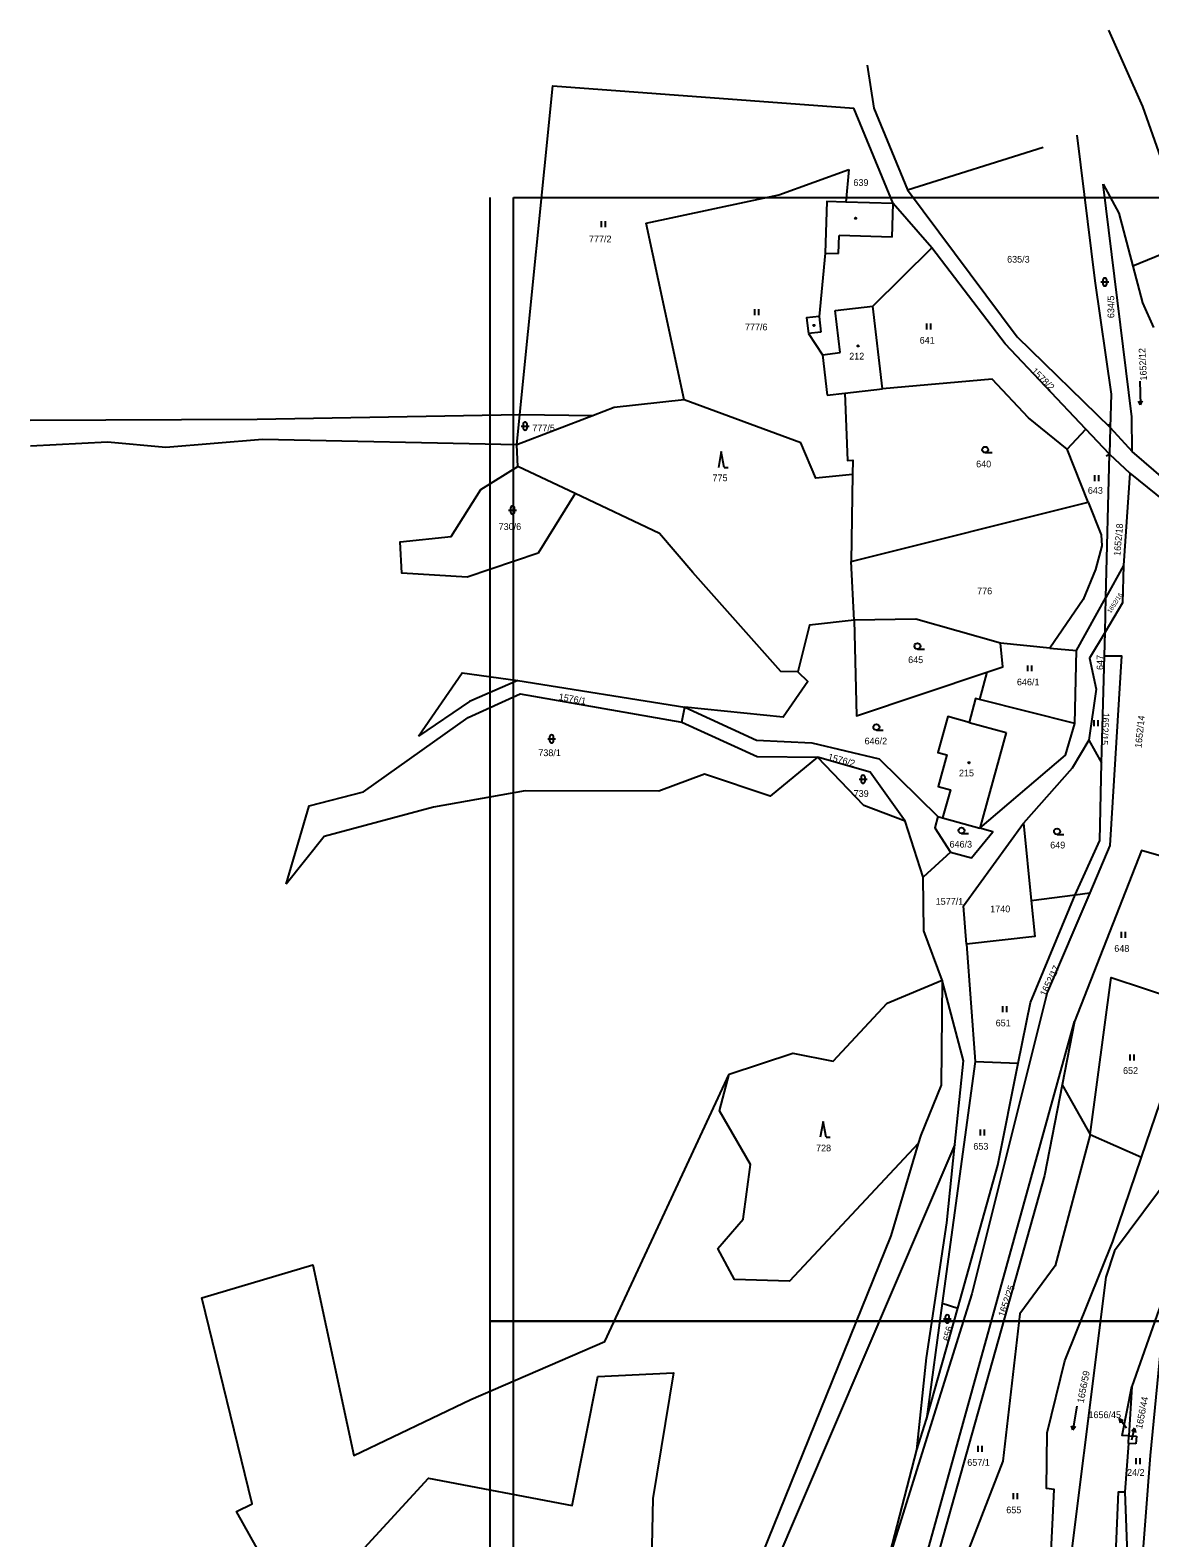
# Model space of a CAD drawing. Extents: x -553916 to -552953, y -1067470 to -1066637.
# Drawn here: x -553916.1 to -553633.4, y -1067154.7 to -1066774 of the extents above; entities that cross this region are included whole.
import ezdxf

# ---------------------------------------------------------------- set-up
doc = ezdxf.new("R2010")
doc.units = 0
for name, color, linetype in [('Hranice parcel', 7, 'Continuous'), ('Parcelní čísla', 7, 'Continuous'), ('Pop  PČ popisy', 7, 'Continuous'), ('Vnitřní kresba', 7, 'Continuous'), ('Vrstva 1', 7, 'Continuous'), ('Značky budov', 7, 'Continuous'), ('Značky kultur', 7, 'Continuous')]:
    doc.layers.add(name, color=color, linetype=linetype)

msp = doc.modelspace()

# ---------------------------------------------------------------- linework, layer by layer
at = {"layer": 'Hranice parcel'}
for p, q in [((-553698.19, -1066817.82), (-553708.14, -1066793.72)), ((-553694.61, -1066814.35), (-553660.35, -1066803.56)), ((-553727.1, -1066815.64), (-553709.46, -1066809.18)), ((-553709.46, -1066809.18), (-553710.17, -1066817.45)), ((-553760.56, -1066822.8), (-553727.1, -1066815.64)), ((-553698.19, -1066817.82), (-553710.17, -1066817.45)), ((-553688.48, -1066828.98), (-553698.19, -1066817.82)), ((-553750.96, -1066867.38), (-553760.56, -1066822.8)), ((-553623.67, -1066827.87), (-553637.71, -1066833.62)), ((-553710.42, -1066865.69), (-553700.89, -1066864.57)), ((-553714.89, -1066866.21), (-553710.42, -1066865.69)), ((-553793.21, -1066878.75), (-553792.44, -1066871.07)), ((-553773.88, -1066871.32), (-553793.21, -1066878.75)), ((-553792.44, -1066871.07), (-553773.88, -1066871.32)), ((-553654.33, -1066879.84), (-553649.57, -1066874.82)), ((-553643.58, -1066881.05), (-553649.57, -1066874.82)), ((-553643.41, -1066874.34), (-553637.93, -1066880.39)), ((-553792.95, -1066884.2), (-553793.21, -1066878.75)), ((-553648.98, -1066893.19), (-553654.33, -1066879.84)), ((-553629.4, -1066887.71), (-553637.93, -1066880.39)), ((-553778.5, -1066891.03), (-553792.95, -1066884.2)), ((-553644.51, -1066917.3), (-553643.58, -1066881.05)), ((-553643.58, -1066881.05), (-553638.51, -1066885.89)), ((-553708.48, -1066886.24), (-553708.86, -1066908.17)), ((-553638.51, -1066885.89), (-553640.1, -1066909.21)), ((-553708.86, -1066908.17), (-553648.98, -1066893.19)), ((-553708.1, -1066923.04), (-553708.86, -1066908.17)), ((-553640.1, -1066909.21), (-553644.51, -1066917.3)), ((-553651.92, -1066930.68), (-553644.51, -1066917.3)), ((-553644.74, -1066926.04), (-553644.51, -1066917.3)), ((-553644.89, -1066931.97), (-553644.74, -1066926.04)), ((-553658.66, -1066930.04), (-553671.16, -1066928.84)), ((-553658.66, -1066930.04), (-553651.92, -1066930.68)), ((-553652.33, -1066949.09), (-553651.92, -1066930.68)), ((-553645.59, -1066958.99), (-553644.89, -1066931.97)), ((-553674.58, -1066936.12), (-553676.4, -1066943.07)), ((-553793.02, -1066938.22), (-553750.82, -1066944.94)), ((-553751.58, -1066948.77), (-553750.82, -1066944.94)), ((-553652.33, -1066949.09), (-553676.4, -1066943.07)), ((-553648.85, -1066953.28), (-553645.59, -1066958.99)), ((-553690.64, -1066987.88), (-553695.17, -1066973.73)), ((-553686.98, -1066972.56), (-553685.74, -1066972.91)), ((-553685.74, -1066972.91), (-553676.37, -1066975.51)), ((-553665.3, -1066974.22), (-553663.36, -1066993.83)), ((-553683.73, -1066981.56), (-553690.64, -1066987.88)), ((-553663.36, -1066993.83), (-553652.32, -1066992.37)), ((-553652.32, -1066992.37), (-553648.57, -1066991.82)), ((-553679.73, -1067004.79), (-553677.51, -1067034.42)), ((-553652.47, -1067024.37), (-553655.53, -1067040.29)), ((-553677.51, -1067034.42), (-553685.85, -1067095.42)), ((-553677.51, -1067034.42), (-553666.64, -1067034.88)), ((-553655.53, -1067040.29), (-553648.45, -1067052.9)), ((-553682.64, -1067055.36), (-553736.85, -1067182.11)), ((-553648.45, -1067052.9), (-553635.52, -1067058.6)), ((-553642.79, -1067079.87), (-553635.52, -1067058.6)), ((-553685.85, -1067095.42), (-553689.85, -1067124.72)), ((-553689.85, -1067124.72), (-553681.91, -1067096.73)), ((-553685.85, -1067095.42), (-553681.91, -1067096.73)), ((-553637.98, -1067116.48), (-553638.7, -1067128.96)), ((-553692.26, -1067132.51), (-553689.85, -1067124.72)), ((-553638.81, -1067130.87), (-553639.7, -1067143.1)), ((-553638.81, -1067130.87), (-553638.7, -1067128.96)), ((-553636.94, -1067130.98), (-553638.81, -1067130.87)), ((-553638.7, -1067128.96), (-553636.8, -1067129.04)), ((-553636.8, -1067129.04), (-553636.94, -1067130.98)), ((-553699.64, -1067161.1), (-553692.26, -1067132.51)), ((-553639.7, -1067143.1), (-553638.95, -1067163.99))]:
    msp.add_line(p, q, dxfattribs=at)
for points in [[(-553643.88, -1066774.03), (-553635.29, -1066793.34), (-553625.66, -1066820.5)], [(-553704.82, -1066782.89), (-553703.1, -1066793.75), (-553694.61, -1066814.35)], [(-553792.44, -1066871.07), (-553784.13, -1066788.1), (-553708.14, -1066793.72)], [(-553651.89, -1066800.53), (-553647.31, -1066837.34), (-553643.19, -1066865.93), (-553643.41, -1066874.34)], [(-553694.61, -1066814.35), (-553666.95, -1066851.46), (-553643.41, -1066874.34)], [(-553637.93, -1066880.39), (-553637.95, -1066871.66), (-553645.19, -1066812.95)], [(-553645.19, -1066812.95), (-553641.24, -1066820.26), (-553637.71, -1066833.62)], [(-553710.17, -1066817.45), (-553715.01, -1066817.3), (-553715.41, -1066830.35), (-553716.91, -1066846.31), (-553720.09, -1066846.68), (-553719.63, -1066850.66)], [(-553700.89, -1066864.57), (-553703.32, -1066843.72), (-553688.48, -1066828.98)], [(-553649.57, -1066874.82), (-553669.94, -1066853.22), (-553688.48, -1066828.98)], [(-553637.71, -1066833.62), (-553635.67, -1066841.32), (-553635.29, -1066842.84), (-553632.51, -1066849.1)], [(-553719.63, -1066850.66), (-553716.09, -1066855.98), (-553714.89, -1066866.21)], [(-553654.33, -1066879.84), (-553664.06, -1066871.9), (-553673.22, -1066862.17), (-553700.89, -1066864.57)], [(-553750.96, -1066867.38), (-553768.66, -1066869.31), (-553773.88, -1066871.32)], [(-553708.48, -1066886.24), (-553717.76, -1066887.14), (-553721.5, -1066878.2), (-553750.96, -1066867.38)], [(-553710.42, -1066865.69), (-553709.75, -1066882.68), (-553708.42, -1066882.64), (-553708.48, -1066886.24)], [(-553916.1, -1066872.49), (-553858.75, -1066872.29), (-553792.44, -1066871.07)], [(-553793.21, -1066878.75), (-553857.42, -1066877.37), (-553881.82, -1066879.37), (-553896.57, -1066878.03), (-553915.98, -1066879.03)], [(-553778.5, -1066891.03), (-553787.89, -1066906.11), (-553805.77, -1066912.16), (-553822.27, -1066911.17), (-553822.69, -1066903.26), (-553809.84, -1066901.91), (-553802.35, -1066890.01), (-553792.95, -1066884.2)], [(-553638.51, -1066885.89), (-553629.69, -1066892.95), (-553626.61, -1066895.43)], [(-553722.33, -1066936.07), (-553726.59, -1066935.94), (-553748.79, -1066910.99), (-553757.18, -1066901.11), (-553778.5, -1066891.03)], [(-553648.98, -1066893.19), (-553645.71, -1066901.42), (-553645.52, -1066904.26), (-553647.18, -1066910.25), (-553650.27, -1066917.79), (-553658.66, -1066930.04)], [(-553640.1, -1066909.21), (-553640.34, -1066918.66), (-553644.74, -1066926.04)], [(-553708.1, -1066923.04), (-553719.33, -1066924.26), (-553722.33, -1066936.07)], [(-553671.16, -1066928.84), (-553692.53, -1066922.74), (-553708.1, -1066923.04)], [(-553708.1, -1066923.04), (-553707.52, -1066947.12), (-553674.58, -1066936.12)], [(-553644.74, -1066926.04), (-553648.66, -1066932.61), (-553646.94, -1066940.41), (-553648.85, -1066953.28)], [(-553674.58, -1066936.12), (-553670.5, -1066934.76), (-553671.16, -1066928.84)], [(-553644.89, -1066931.97), (-553640.62, -1066932.03), (-553643.49, -1066979.92), (-553648.57, -1066991.82)], [(-553818.03, -1066952.27), (-553807.07, -1066936.29), (-553793.02, -1066938.22)], [(-553722.33, -1066936.07), (-553719.8, -1066938.45), (-553726.01, -1066947.52), (-553750.82, -1066944.94)], [(-553793.02, -1066938.22), (-553805.16, -1066943.52), (-553818.03, -1066952.27)], [(-553851.45, -1066989.66), (-553845.69, -1066969.91), (-553831.91, -1066966.35), (-553805.48, -1066947.58), (-553792.42, -1066941.62), (-553751.58, -1066948.77)], [(-553750.82, -1066944.94), (-553732.69, -1066953.28), (-553718.72, -1066954.01), (-553701.74, -1066958), (-553686.98, -1066972.56)], [(-553676.4, -1066943.07), (-553677.43, -1066942.81), (-553679, -1066948.83), (-553684.45, -1066947.32), (-553686.97, -1066956.38), (-553684.65, -1066957.02), (-553686.87, -1066965.02), (-553683.79, -1066965.88), (-553685.74, -1066972.91)], [(-553751.58, -1066948.77), (-553732.58, -1066957.42), (-553717.29, -1066957.56)], [(-553676.37, -1066975.51), (-553654.76, -1066957.08), (-553652.33, -1066949.09)], [(-553648.85, -1066953.28), (-553653.03, -1066960.38), (-553665.3, -1066974.22)], [(-553717.29, -1066957.56), (-553729.27, -1066967.46), (-553745.82, -1066961.92), (-553757.37, -1066966.16), (-553791.09, -1066966.12), (-553814.24, -1066970.19), (-553841.88, -1066977.67), (-553851.45, -1066989.66)], [(-553695.17, -1066973.73), (-553705.64, -1066969.81), (-553717.29, -1066957.56)], [(-553695.17, -1066973.73), (-553704.05, -1066961.37), (-553717.29, -1066957.56)], [(-553652.32, -1066992.37), (-553646.09, -1066978.61), (-553645.59, -1066958.99)], [(-553686.98, -1066972.56), (-553687.7, -1066975.46), (-553683.73, -1066981.56)], [(-553683.73, -1066981.56), (-553678.45, -1066983.01), (-553673.1, -1066976.42), (-553676.37, -1066975.51)], [(-553679.73, -1067004.79), (-553680.45, -1066995.12), (-553665.3, -1066974.22)], [(-553627.02, -1066983.6), (-553635.52, -1066981.16), (-553652.47, -1067024.37)], [(-553623.32, -1066984.67), (-553619.63, -1066996.83), (-553619.56, -1067023.02), (-553621.7, -1067038.64), (-553627.75, -1067062.69), (-553642.34, -1067082.27), (-553644.52, -1067088.87), (-553655.73, -1067178.24), (-553657.73, -1067185.13), (-553660.17, -1067189.87)], [(-553685.87, -1067013.91), (-553690.5, -1067001.43), (-553690.64, -1066987.88)], [(-553648.57, -1066991.82), (-553659.32, -1067017.01), (-553678.4, -1067093.07), (-553699.64, -1067161.1)], [(-553663.36, -1066993.83), (-553662.49, -1067002.88), (-553679.73, -1067004.79)], [(-553666.64, -1067034.88), (-553663.56, -1067019.54), (-553652.32, -1066992.37)], [(-553648.45, -1067052.9), (-553643.22, -1067013.2), (-553625.87, -1067018.94)], [(-553739.65, -1067037.62), (-553723.52, -1067032.31), (-553713.35, -1067034.36), (-553699.72, -1067019.75), (-553685.87, -1067013.91)], [(-553685.87, -1067013.91), (-553686.09, -1067040.42), (-553691.28, -1067053.08), (-553691.88, -1067055.11)], [(-553682.64, -1067055.36), (-553680.47, -1067034.25), (-553685.87, -1067013.91)], [(-553635.52, -1067058.6), (-553624.9, -1067027.54), (-553625.87, -1067018.94)], [(-553695.94, -1067227.92), (-553697.09, -1067200.45), (-553693.46, -1067172.18), (-553652.47, -1067024.37)], [(-553681.91, -1067096.73), (-553671.8, -1067060.62), (-553666.64, -1067034.88)], [(-553856.98, -1067179.12), (-553855.63, -1067163.09), (-553864, -1067148.03), (-553860.02, -1067146.13), (-553872.73, -1067094.13), (-553844.72, -1067085.79), (-553834.37, -1067133.89), (-553804.82, -1067119.79), (-553771, -1067105.16), (-553739.65, -1067037.62)], [(-553691.88, -1067055.11), (-553724.41, -1067089.91), (-553738.29, -1067089.46), (-553742.48, -1067081.62), (-553736.1, -1067074.23), (-553734.28, -1067060.42), (-553742.1, -1067046.86), (-553739.65, -1067037.62)], [(-553655.53, -1067040.29), (-553660.05, -1067063.23), (-553688.55, -1067164.71), (-553692.38, -1067192.94), (-553695.94, -1067227.92)], [(-553691.88, -1067055.11), (-553698.79, -1067078.47), (-553744.69, -1067191.8)], [(-553692.26, -1067132.51), (-553689.81, -1067109.27), (-553684.68, -1067075.16), (-553682.64, -1067055.36)], [(-553648.45, -1067052.9), (-553657.29, -1067086.06), (-553666.21, -1067098.13), (-553670.52, -1067135.37), (-553684.51, -1067171.37), (-553689.91, -1067228.79)], [(-553660.17, -1067189.87), (-553659.36, -1067184.27), (-553658.56, -1067162.92), (-553658, -1067151.36), (-553657.6, -1067142.52), (-553659.52, -1067142.26), (-553659.32, -1067128.21), (-553654.86, -1067110.02), (-553642.79, -1067079.87)], [(-553629.28, -1067092.37), (-553631.12, -1067097.14), (-553637.98, -1067116.48)], [(-553629.28, -1067092.37), (-553633.37, -1067133.92), (-553635.66, -1067164.7)], [(-553852.6, -1067180), (-553815.54, -1067139.66), (-553779.26, -1067146.56), (-553772.79, -1067113.94), (-553753.66, -1067113.05), (-553758.92, -1067144.82), (-553759.49, -1067172.72), (-553744.69, -1067191.8)], [(-553638.7, -1067128.96), (-553640.44, -1067128.89), (-553637.98, -1067116.48)], [(-553643.28, -1067188.54), (-553641.31, -1067143.1), (-553639.7, -1067143.1)]]:
    msp.add_lwpolyline(points, dxfattribs=at)
at = {"layer": 'Pop  PČ popisy'}
for p, q in [((-553639.33, -1067126.98), (-553641.14, -1067124.58)), ((-553641.14, -1067124.58), (-553640.13, -1067125.08)), ((-553641.14, -1067124.58), (-553640.93, -1067125.68)), ((-553637.99, -1067129.93), (-553637.26, -1067127.02)), ((-553637.26, -1067127.02), (-553637.99, -1067127.87)), ((-553637.26, -1067127.02), (-553637.02, -1067128.11))]:
    msp.add_line(p, q, dxfattribs=at)
at = {"layer": 'Vnitřní kresba'}
for p, q in [((-553698.45, -1066826.31), (-553698.19, -1066817.82)), ((-553712.02, -1066830.45), (-553711.88, -1066825.9)), ((-553698.45, -1066826.31), (-553711.88, -1066825.9)), ((-553715.41, -1066830.35), (-553712.02, -1066830.45)), ((-553712.86, -1066844.83), (-553703.32, -1066843.72)), ((-553711.62, -1066855.46), (-553712.86, -1066844.83)), ((-553716.91, -1066846.31), (-553716.45, -1066850.28)), ((-553716.45, -1066850.28), (-553719.63, -1066850.66)), ((-553716.09, -1066855.98), (-553711.62, -1066855.46)), ((-553643.77, -1066873.41), (-553643.41, -1066874.34)), ((-553643.41, -1066874.34), (-553643.58, -1066881.05)), ((-553644.45, -1066881.55), (-553643.58, -1066881.05)), ((-553679, -1066948.83), (-553669.71, -1066951.41)), ((-553669.71, -1066951.41), (-553676.37, -1066975.51))]:
    msp.add_line(p, q, dxfattribs=at)
at = {"layer": 'Vrstva 1'}
for p, q in [((-553794.11, -1067410.27), (-553794.11, -1066816.27)), ((-553794.11, -1066816.27), (-552953.11, -1066816.27))]:
    msp.add_line(p, q, dxfattribs=at)
for points in [[(-553300, -1066816.27), (-553300, -1067100), (-553800, -1067100), (-553800, -1066816.27)], [(-553800, -1067410.27), (-553800, -1067100), (-553300, -1067100), (-553300, -1067410.27)]]:
    msp.add_lwpolyline(points, dxfattribs=at)
at = {"layer": 'Značky budov'}
for centre in [(-553707.7, -1066821.53), (-553718.22, -1066848.59), (-553707.07, -1066853.75), (-553679.08, -1066959.01)]:
    msp.add_circle(centre, 0.175, dxfattribs=at)
at = {"layer": 'Značky kultur'}
for p, q in [((-553771.87, -1066823.75), (-553771.87, -1066822.25)), ((-553770.87, -1066823.75), (-553770.87, -1066822.25)), ((-553645.79, -1066837.61), (-553643.79, -1066837.61)), ((-553645.29, -1066837.11), (-553645.29, -1066838.11)), ((-553644.29, -1066838.11), (-553644.29, -1066837.11)), ((-553733.13, -1066845.96), (-553733.13, -1066844.46)), ((-553732.13, -1066845.96), (-553732.13, -1066844.46)), ((-553689.71, -1066849.63), (-553689.71, -1066848.13)), ((-553688.71, -1066849.63), (-553688.71, -1066848.13)), ((-553635.98, -1066862.64), (-553635.77, -1066868.64)), ((-553635.77, -1066868.64), (-553636.31, -1066867.68)), ((-553635.77, -1066868.64), (-553635.31, -1066867.64)), ((-553792.14, -1066874), (-553790.14, -1066874)), ((-553791.64, -1066873.5), (-553791.64, -1066874.5)), ((-553790.64, -1066874.5), (-553790.64, -1066873.5)), ((-553741.61, -1066880.43), (-553742.36, -1066884.43)), ((-553740.86, -1066884.43), (-553741.61, -1066880.43)), ((-553675.01, -1066880.71), (-553673.26, -1066880.71)), ((-553740.86, -1066884.43), (-553739.86, -1066884.43)), ((-553647.32, -1066887.89), (-553647.32, -1066886.39)), ((-553646.32, -1066887.89), (-553646.32, -1066886.39)), ((-553795.31, -1066895.2), (-553793.31, -1066895.2)), ((-553794.81, -1066894.7), (-553794.81, -1066895.7)), ((-553793.81, -1066895.7), (-553793.81, -1066894.7)), ((-553692.1, -1066930.3), (-553690.35, -1066930.3)), ((-553664.19, -1066935.92), (-553664.19, -1066934.42)), ((-553663.19, -1066935.92), (-553663.19, -1066934.42)), ((-553647.46, -1066949.78), (-553647.46, -1066948.28)), ((-553646.46, -1066949.78), (-553646.46, -1066948.28)), ((-553784.95, -1066952.48), (-553784.95, -1066953.48)), ((-553783.95, -1066953.48), (-553783.95, -1066952.48)), ((-553702.46, -1066950.79), (-553700.71, -1066950.79)), ((-553785.45, -1066952.98), (-553783.45, -1066952.98)), ((-553706.83, -1066963.16), (-553704.83, -1066963.16)), ((-553706.33, -1066962.66), (-553706.33, -1066963.66)), ((-553705.33, -1066963.66), (-553705.33, -1066962.66)), ((-553680.98, -1066976.87), (-553679.23, -1066976.87)), ((-553656.85, -1066977.1), (-553655.1, -1066977.1)), ((-553640.58, -1067003.2), (-553640.58, -1067001.7)), ((-553639.58, -1067003.2), (-553639.58, -1067001.7)), ((-553670.54, -1067022.01), (-553670.54, -1067020.51)), ((-553669.54, -1067022.01), (-553669.54, -1067020.51)), ((-553638.37, -1067034.2), (-553638.37, -1067032.7)), ((-553637.37, -1067034.2), (-553637.37, -1067032.7)), ((-553715.92, -1067049.57), (-553716.67, -1067053.57)), ((-553715.17, -1067053.57), (-553715.92, -1067049.57)), ((-553676.17, -1067053.15), (-553676.17, -1067051.65)), ((-553675.17, -1067053.15), (-553675.17, -1067051.65)), ((-553715.17, -1067053.57), (-553714.17, -1067053.57)), ((-553685.56, -1067099.43), (-553683.56, -1067099.43)), ((-553685.06, -1067098.93), (-553685.06, -1067099.93)), ((-553684.06, -1067099.93), (-553684.06, -1067098.93)), ((-553651.89, -1067121.5), (-553652.83, -1067127.43)), ((-553652.83, -1067127.43), (-553653.17, -1067126.39)), ((-553652.83, -1067127.43), (-553652.18, -1067126.54)), ((-553676.73, -1067132.98), (-553676.73, -1067131.48)), ((-553675.73, -1067132.98), (-553675.73, -1067131.48)), ((-553636.91, -1067136.12), (-553636.91, -1067134.62)), ((-553635.91, -1067136.12), (-553635.91, -1067134.62)), ((-553667.85, -1067144.96), (-553667.85, -1067143.46)), ((-553666.85, -1067144.96), (-553666.85, -1067143.46))]:
    msp.add_line(p, q, dxfattribs=at)
for centre in [(-553675.01, -1066879.96), (-553692.1, -1066929.55), (-553702.46, -1066950.04), (-553680.98, -1066976.12), (-553656.85, -1066976.35)]:
    msp.add_circle(centre, 0.75, dxfattribs=at)
for centre, start, end in [((-553644.79, -1066837.11), 0, 180), ((-553644.79, -1066838.11), 180, 359.9879), ((-553791.14, -1066873.5), 0, 180), ((-553791.14, -1066874.5), 180, 359.9879), ((-553794.31, -1066894.7), 0, 180), ((-553794.31, -1066895.7), 180, 359.9879), ((-553784.45, -1066952.48), 0, 180), ((-553784.45, -1066953.48), 180, 359.9879), ((-553705.83, -1066962.66), 0, 180), ((-553705.83, -1066963.66), 180, 359.9879), ((-553684.56, -1067098.93), 0, 180), ((-553684.56, -1067099.93), 180, 359.9879)]:
    msp.add_arc(centre, 0.5, start, end, dxfattribs=at)

# ---------------------------------------------------------------- texts
at = {"layer": 'Parcelní čísla'}
for s, p in [('639', (-553708.26, -1066813.36)), ('777/2', (-553775.03, -1066827.6)), ('635/3', (-553669.46, -1066832.73)), ('777/6', (-553735.64, -1066849.83)), ('641', (-553691.53, -1066853.18)), ('212', (-553709.32, -1066857.2)), ('777/5', (-553789.32, -1066875.32)), ('640', (-553677.28, -1066884.42)), ('775', (-553743.83, -1066887.91)), ('643', (-553649.07, -1066891.09)), ('730/6', (-553797.83, -1066900.23)), ('776', (-553677.03, -1066916.48)), ('645', (-553694.44, -1066933.85)), ('646/1', (-553666.98, -1066939.47)), ('646/2', (-553705.44, -1066954.37)), ('738/1', (-553787.81, -1066957.34)), ('215', (-553681.62, -1066962.45)), ('739', (-553708.2, -1066967.62)), ('646/3', (-553684, -1066980.43)), ('649', (-553658.58, -1066980.65)), ('1577/1', (-553687.49, -1066994.87)), ('1740', (-553673.72, -1066996.76)), ('648', (-553642.4, -1067006.75)), ('651', (-553672.35, -1067025.56)), ('652', (-553640.19, -1067037.58)), ('728', (-553717.69, -1067057.12)), ('653', (-553677.98, -1067056.7)), ('1656/45', (-553648.92, -1067124.49)), ('657/1', (-553679.52, -1067136.53)), ('24/2', (-553639.18, -1067139.06)), ('655', (-553669.67, -1067148.51))]:
    msp.add_text(s, height=1.7, dxfattribs=at).set_placement(p)
for s, height, rotation, p in [('634/5', 1.7, 90, (-553642.41, -1066846.74)), ('1652/12', 1.7, 93, (-553634.14, -1066862.46)), ('1578/2', 1.7, 316, (-553663.5, -1066860.33)), ('1652/18', 1.7, 85, (-553640.88, -1066906.84)), ('1652/16', 1.14, 57, (-553643.32, -1066921.35)), ('647', 1.7, 90, (-553645.15, -1066935.58)), ('1576/1', 1.7, 350, (-553782.76, -1066943.13)), ('1652/15', 1.7, 267, (-553645.34, -1066946.31)), ('1652/14', 1.7, 84, (-553635.53, -1066955.34)), ('1576/2', 1.7, 345, (-553714.84, -1066958.27)), ('1652/17', 1.7, 64, (-553659.73, -1067018.1)), ('1652/25', 1.7, 71, (-553670.16, -1067099.05)), ('656', 1.7, 77, (-553684.01, -1067105.17)), ('1656/59', 1.7, 79, (-553650.14, -1067120.79)), ('1656/44', 1.7, 79, (-553635.39, -1067127.33))]:
    msp.add_text(s, height=height, rotation=rotation, dxfattribs=at).set_placement(p)

doc.saveas('drawing.dxf')
